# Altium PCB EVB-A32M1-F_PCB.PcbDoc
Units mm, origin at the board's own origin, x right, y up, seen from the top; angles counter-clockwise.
Board outline 51 x 21 mm, 4 copper layers (L1 (Signal), L2 (GND), L3 (PWR), L4 (Signal)), stack 1.586 mm thick; 29 components, 45 nets, 292 pads, 57 vias.
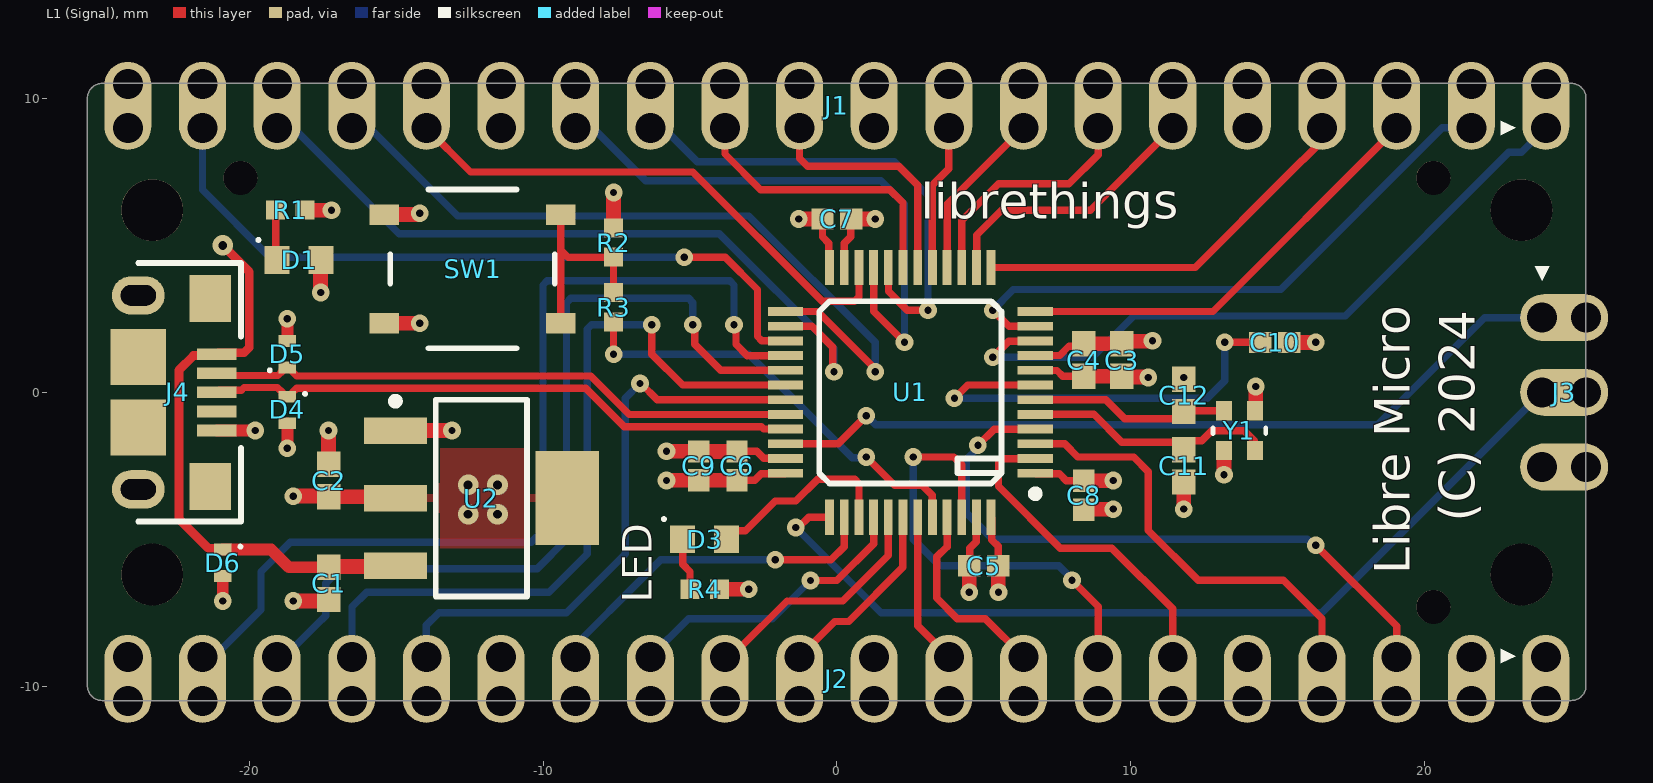
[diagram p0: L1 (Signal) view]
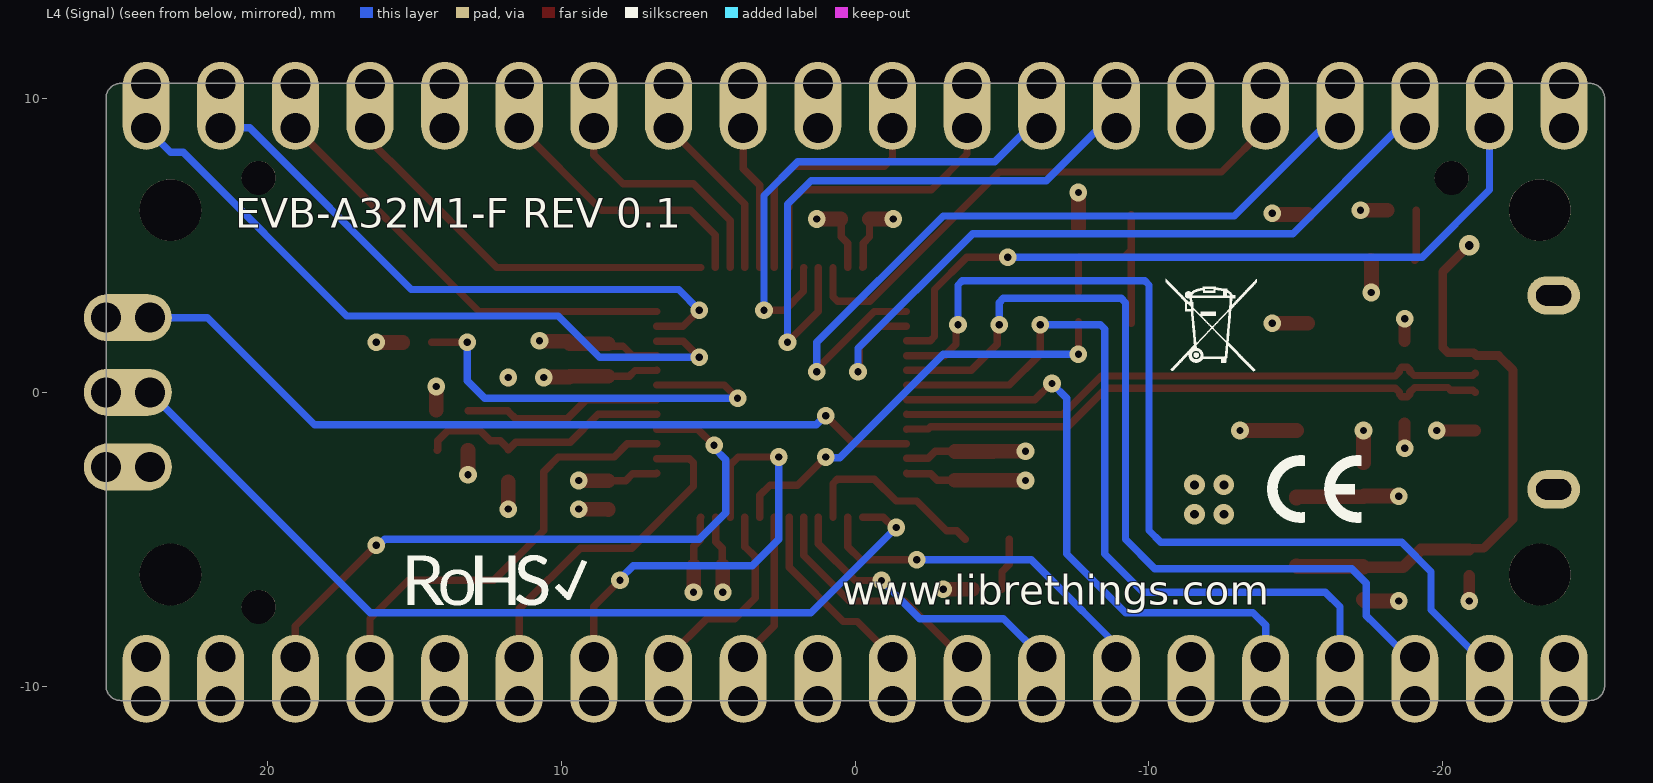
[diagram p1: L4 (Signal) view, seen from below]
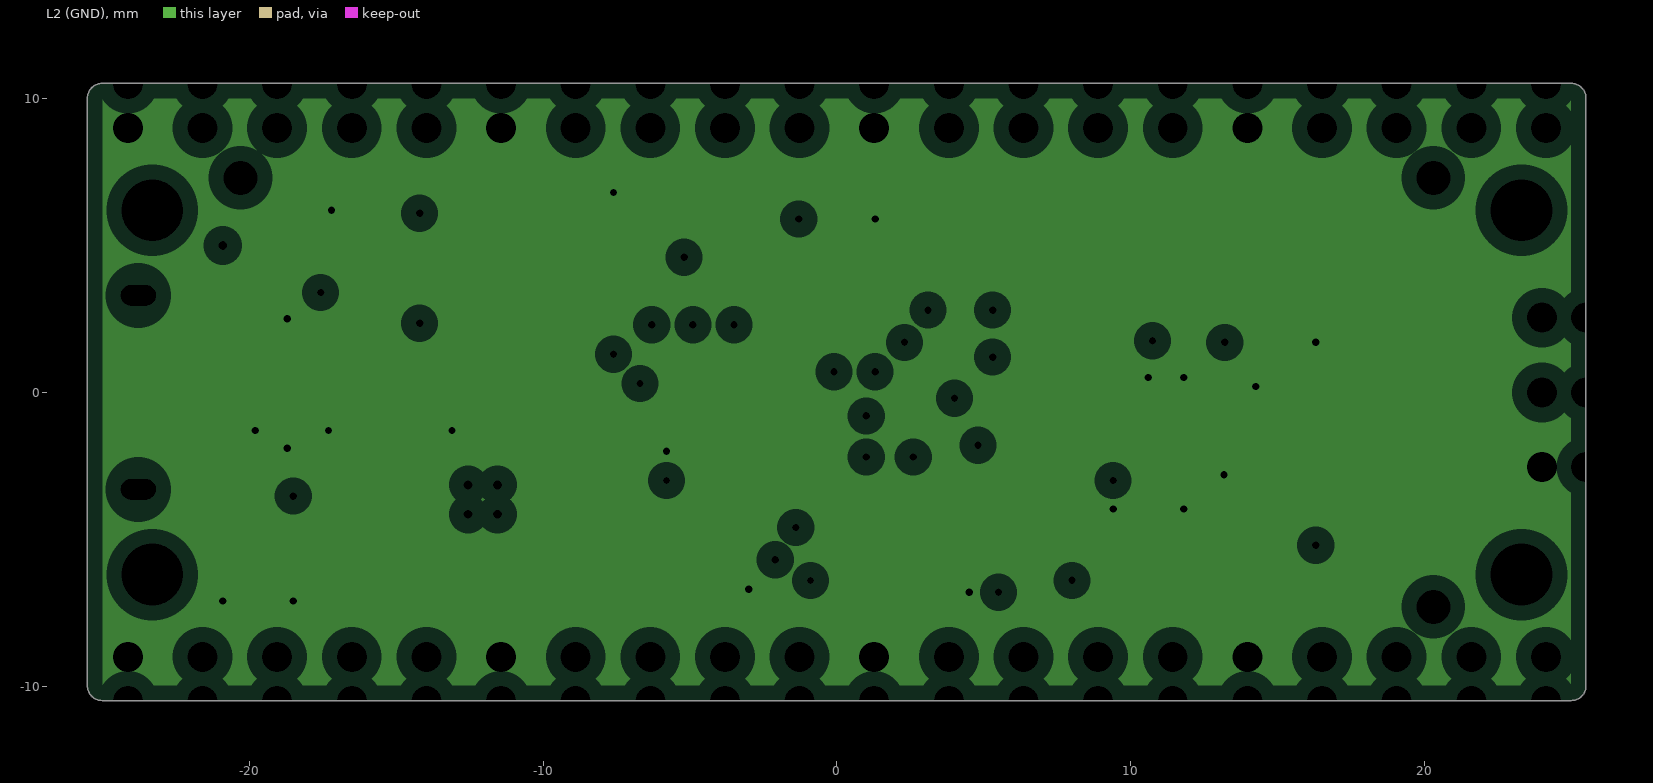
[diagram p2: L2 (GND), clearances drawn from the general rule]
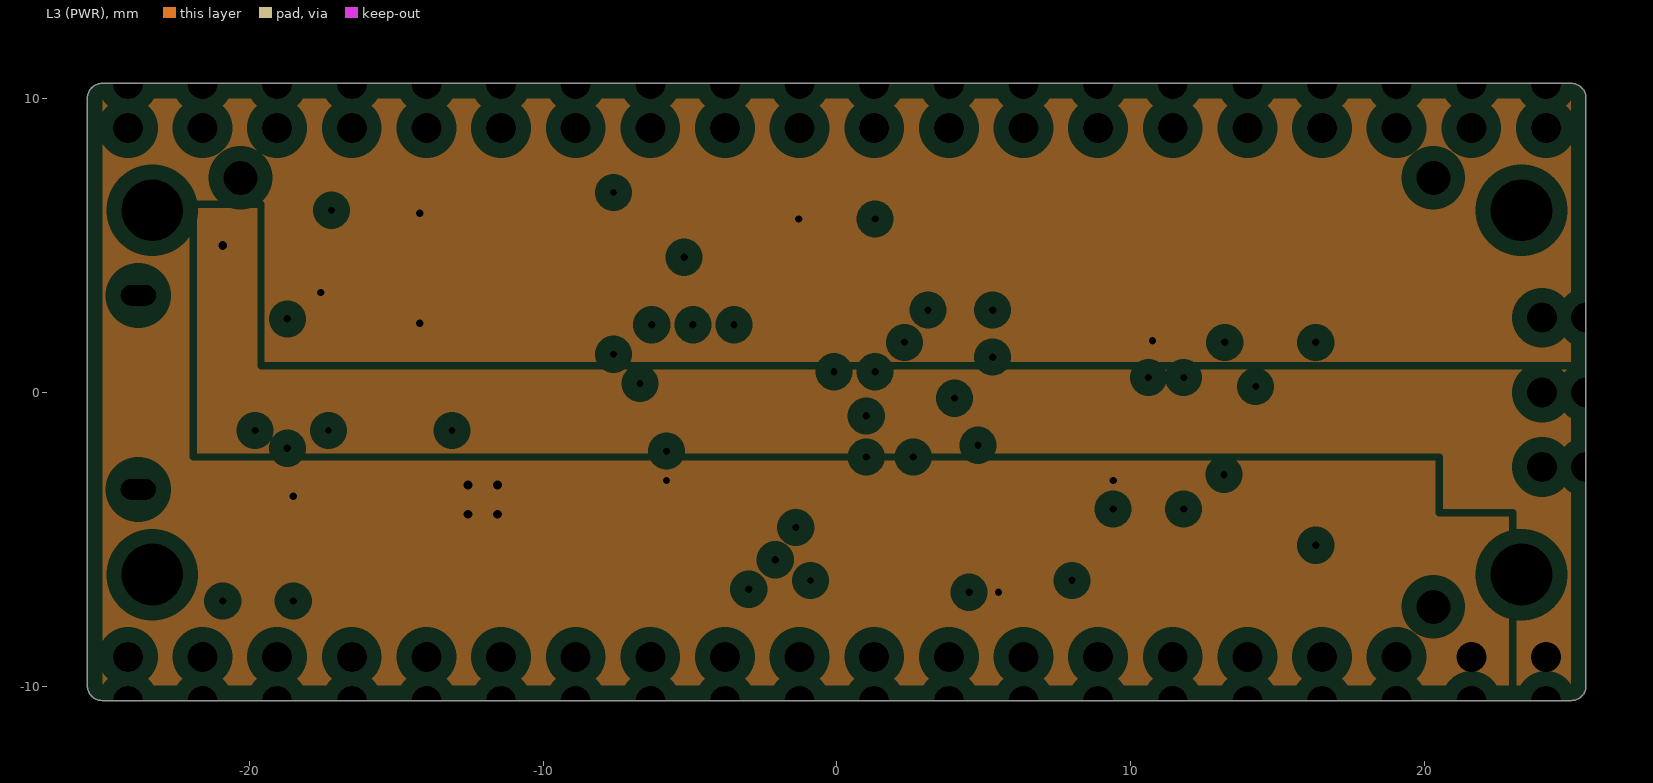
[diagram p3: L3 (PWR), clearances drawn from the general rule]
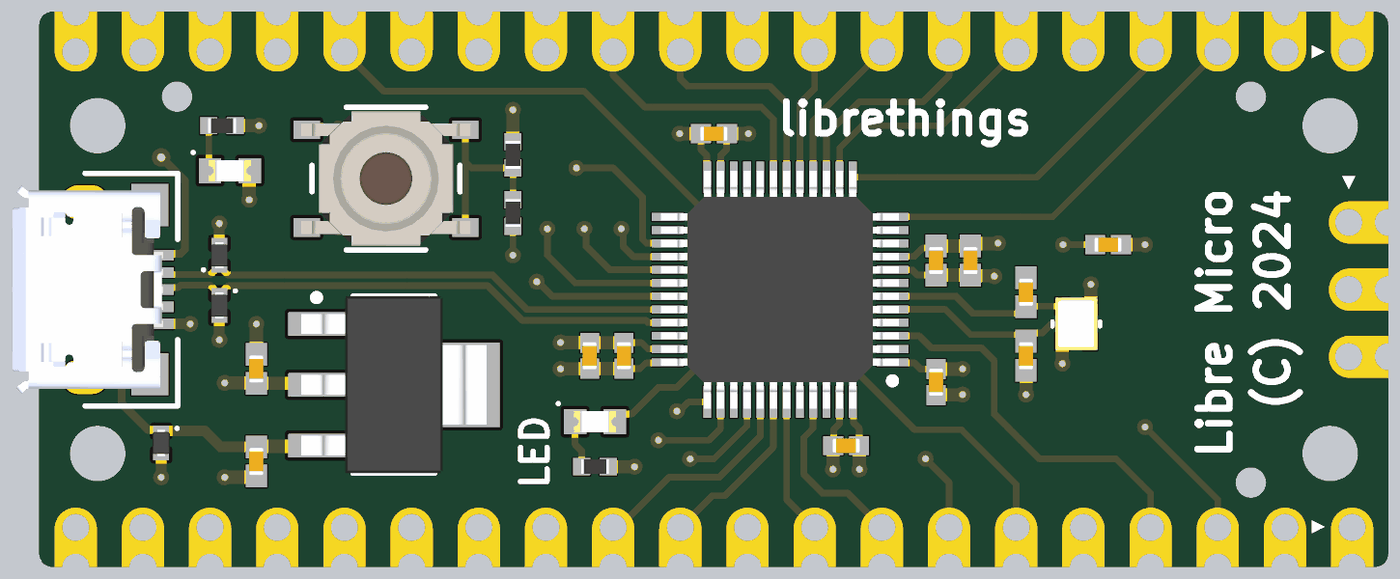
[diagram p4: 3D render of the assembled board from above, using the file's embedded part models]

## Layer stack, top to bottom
Top Solder: solder mask 0.0152, JLC-001, Dk 3.8
L1 (Signal): signal copper 0.035
PP1_7628: prepreg 0.2104, Nan Ya Plastics NP-155F 7628, Dk 4.4
L2 (GND): plane copper 0.0152, net GND
C_FR4: core 1.065, Nan Ya Plastics NP-155F FR4 / 5-7628, Dk 4.6
L3 (PWR): plane copper 0.0152, net +3V3
PP2_7628: prepreg 0.2104, Nan Ya Plastics NP-155F 7628, Dk 4.4
L4 (Signal): signal copper 0.035
Bottom Solder: solder mask 0.0152, JLC-001, Dk 3.8

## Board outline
-25.507,-9.987 -25.507,10.013 cw(c-25.007,10.013) -25.007,10.513 24.993,10.513 cw(c24.993,10.013) 25.493,10.013 25.493,-9.987 cw(c24.993,-9.987) 24.993,-10.487 -25.007,-10.487 cw(c-25.007,-9.987)

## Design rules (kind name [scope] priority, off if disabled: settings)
BoardOutlineClearance [IsText = 'True'] p1: gap=0.3 ignorepadtopadclearanceinfootprint=FALSE
Clearance ClearanceCastellated [InPadClass('Castellated')] p1: gap=0 ignorepadtopadclearanceinfootprint=FALSE
Clearance [All] p2: gap=0.25 ignorepadtopadclearanceinfootprint=FALSE except(0.1: Arc-Arc Arc-Track Track-Track; 0.15: SMDPad-SMDPad; 0.22: Arc-SMDPad Track-SMDPad; 0.27: Arc-Via Arc-Hole Track-Via Track-Hole; 0.5: THPad-THPad)
DiffPairsRouting [InDifferentialPairClass('DIFF_USB')] p1: maxlimit=0.16 minlimit=0.16 mostfreqgap=0.16 toplayer_minwidth=0.25 toplayer_maxwidth=0.25 toplayer_prefwidth=0.25 bottomlayer_minwidth=0.25 bottomlayer_maxwidth=0.25 bottomlayer_prefwidth=0.25 impedanceprofiledriven=TRUE impedanceprofileid={08012B50-AAB2-4C45-ABE7-EA8999D4259F} impedanceprofilevalue=90.000000 maxuncoupledlength=12.7
HoleSize NPTHSlotSize [HoleType = 'Slot' && PadIsPlated = 'False'] p1: absolutevalues=TRUE maxlimit=5.6 minlimit=1 maxpercent=80.000 minpercent=20.000
HoleSize PTHSlotSize [HoleType = 'Slot' && PadIsPlated = 'True'] p2: absolutevalues=TRUE maxlimit=5.6 minlimit=0.5 maxpercent=80.000 minpercent=20.000
HoleSize PTHSize [PadIsPlated = 'True'] p3: absolutevalues=TRUE maxlimit=6.35 minlimit=0.2 maxpercent=80.000 minpercent=20.000
HoleSize NPTHSize [PadIsPlated = 'False'] p4: absolutevalues=TRUE maxlimit=6.3 minlimit=0.2 maxpercent=80.000 minpercent=20.000
HoleToHoleClearance HoleToHoleClearanceCastellated [InPadClass('Castellated')] p1: gap=0.254 allowstackedmicrovias=TRUE
HoleToHoleClearance [All] p2: gap=0.5 allowstackedmicrovias=TRUE
MinimumAnnularRing MinimumAnnularRingCastellated [InPadClass('Castellated')] p1: minimumring=0
MinimumAnnularRing PTHSlotMinimumAnnularRing_1 [HoleType = 'Slot' && PadIsPlated = 'True'] p2: minimumring=0.3
MinimumAnnularRing PTHMinimumAnnularRing [PadIsPlated = 'True'] p3: minimumring=0.3
MinimumAnnularRing ViaMinimumAnnularRing [IsVia] p4: minimumring=0.15
MinimumSolderMaskSliver [All] p1: minsoldermaskwidth=0.1
PlaneClearance [All] p1: clearance=0.508
PlaneConnect [All] p1: pad.planeconnectstyle=Relief pad.reliefexpansion=0.508 pad.reliefentries=4 pad.reliefconductorwidth=0.254 pad.reliefairgap=0.254 via.planeconnectstyle=Direct via.reliefexpansion=0.508 via.reliefentries=4 via.reliefconductorwidth=0.254 via.reliefairgap=0.254
PolygonConnect [All] p1: thpad.connectstyle=Relief thpad.reliefconductorwidth=0.254 thpad.reliefentries=4 thpad.polygonreliefangle="90 Angle" thpad.airgapwidth=0.254 smdpad.connectstyle=Relief smdpad.reliefconductorwidth=0.254 smdpad.reliefentries=4 smdpad.polygonreliefangle="90 Angle" smdpad.airgapwidth=0.254 via.connectstyle=Direct via.reliefconductorwidth=0.254 via.reliefentries=4 via.polygonreliefangle="90 Angle" via.airgapwidth=0.254
RoutingVias [All] p1: holewidth=0.25 width=0.6 viastyle="Through Hole" minholewidth=0.2 minwidth=0.5 maxholewidth=0.3 maxwidth=0.7
ShortCircuit ShortCircuitCastellated [InPadClass('Castellated')] p1: allowed=TRUE
ShortCircuit [All] p2: allowed=FALSE
SilkToSilkClearance [All] p1: silktosilkclearance=0.3
SilkToSolderMaskClearance [IsPad] p1: minsilkscreentomaskgap=0.15 clearancetoexposedcopper=TRUE
SolderMaskExpansion [All] p1: expansion=0.127 istentingtop=FALSE
SupplyNets "Schematic Supply Nets_5" [InNet('VBUS')] p1: voltage=0.000
SupplyNets "Schematic Supply Nets_4" [InNet('GND')] p2: voltage=0.000
SupplyNets "Schematic Supply Nets" [InNet('+3V3')] p3: voltage=0.000
UnRoutedNet [All] p1: checkbadconnections=TRUE
Width [All] p1: maxlimit=0.5 minlimit=0.1 preferedwidth=0.25
20 further rules are at their usual default settings.

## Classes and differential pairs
pad class Castellated: J1-0 J1-1 J1-1B J1-1T J1-2 J1-2B J1-2T J1-3 J1-3B J1-3T J1-4 J1-4B J1-4T J1-5 J1-5B J1-5T J1-6 J1-6B J1-6T J1-7 J1-7B J1-7T J1-8 J1-8B J1-8T J1-9 J1-9B J1-9T J1-10 J1-10B J1-10T J1-11 J1-11B J1-11T J1-12 J1-12B J1-12T J1-13 J1-13B J1-13T J1-14 J1-14B J1-14T J1-15 J1-15B J1-15T J1-16 J1-16B J1-16T J1-17 J1-17B J1-17T J1-18 J1-18B J1-18T J1-19 J1-19B J1-19T J1-20 J1-20B J1-20T J2-0 J2-1 J2-1B J2-1T J2-2 J2-2B J2-2T J2-3 J2-3B J2-3T J2-4 J2-4B J2-4T J2-5 J2-5B J2-5T J2-6 J2-6B J2-6T J2-7 J2-7B J2-7T J2-8 J2-8B J2-8T J2-9 J2-9B J2-9T J2-10 J2-10B J2-10T J2-11 J2-11B J2-11T J2-12 J2-12B J2-12T J2-13 J2-13B J2-13T J2-14 J2-14B J2-14T J2-15 J2-15B J2-15T J2-16 J2-16B J2-16T J2-17 J2-17B J2-17T J2-18 J2-18B J2-18T J2-19 J2-19B J2-19T J2-20 J2-20B J2-20T J3-0 J3-1 J3-1B J3-1T J3-2 J3-2B J3-2T J3-3 J3-3B J3-3T
differential pair class DIFF_USB: USB_D
differential pair USB_D: +USB_D_P -USB_D_N

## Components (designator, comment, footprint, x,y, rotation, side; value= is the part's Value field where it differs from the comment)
C1 "CC0402MRX5R6BB105" C_Yageo_CC_0402_A -17.3,-6.5 r90 top value=1uF
C2 "CC0402MRX5R6BB105" C_Yageo_CC_0402_A -17.3,-3 r270 top value=1uF
C3 "CC0402MRX5R6BB105" C_Yageo_CC_0402_A 9.7,1.1 r90 top value=1uF
C4 "CC0402KRX7R7BB103" C_Yageo_CC_0402_A 8.4,1.1 r90 top value=10nF
C5 "CL05B104KP5NNNC" C_Samsung_CL_0402_A 5,-5.9 r0 top value=100nF
C6 "CL05B104KP5NNNC" C_Samsung_CL_0402_A -3.4,-2.5 r270 top value=100nF
C7 "CL05B104KP5NNNC" C_Samsung_CL_0402_A 0,5.9 r180 top value=100nF
C8 "CL05B104KP5NNNC" C_Samsung_CL_0402_A 8.4,-3.5 r90 top value=100nF
C9 "CL05A475MP5NRNC" C_Samsung_CL_0402_A -4.7,-2.5 r270 top value=4.7uF
C10 "CL05B104KP5NNNC" C_Samsung_CL_0402_A 14.9,1.7 r180 top value=100nF
C11 "CC0402JRNPO9BN150" C_Yageo_CC_0402_A 11.8,-2.5 r90 top value=15pF
C12 "CC0402JRNPO9BN150" C_Yageo_CC_0402_A 11.8,-0.1 r270 top value=15pF
D1 "LTST-C190GKT" D_LED_Lite-On_Green_0603_A -18.3,4.5 r0 top
D3 "LTST-C190GKT" D_LED_Lite-On_Green_0603_A -4.5,-5 r0 top
D4 "D5V0F1U2S9-7" D_TVS_Uni_Diodes_SOD-923_B -18.7,-0.6 r270 top value=5E-13F
D5 "D5V0F1U2S9-7" D_TVS_Uni_Diodes_SOD-923_B -18.7,1.3 r90 top value=5E-13F
D6 "D5V0F1U2S9-7" D_TVS_Uni_Diodes_SOD-923_B -20.9,-5.8 r270 top value=5E-13F
J1 "PPPC201LFBN-RC" J_Cast_TH20_Top_2.54mm 0,9.75 r180 top
J2 "PPPC201LFBN-RC" J_Cast_TH20_Bottom_2.54mm 0,-9.75 r180 top
J3 "PPPC031LFBN-RC" J_Cast_TH3_Bottom_2.54mm 24.75,0 r270 top
J4 "10118193-0001LF" J_USB_Micro-B_Amphenol_10118193-0001LF -23.775,0 r270 top
R1 "RC0402FR-071KL" R_Yageo_RCL_0402_A -18.6,6.2 r180 top value=1kR
R2 "RC0402FR-0710KL" R_Yageo_RCL_0402_A -7.6,5.1 r270 top value=10kR
R3 "RC0402FR-071KL" R_Yageo_RCL_0402_A -7.6,2.9 r90 top value=1kR
R4 "RC0402FR-071KL" R_Yageo_RCL_0402_A -4.5,-6.7 r180 top value=1kR
SW1 "PTS526SK15SMTR2LFS" "SW_Tactitle_SPST_C&K_PTS526 SK15 SMTR2 LFS" -12.4,4.2 r180 top
U1 "STM32F070CBT6" U_ST_LQFP48_B 2.5,0 r180 top
U2 "TLV1117LV33DCYR" U_TI_SOT-223_B -12.1,-3.6 r0 top
Y1 "ECS-240-12-37B-CKY-TR" Y_Crystal_GND24_ECS_240-12-37B-CKY-TR 13.7,-1.3 r90 top

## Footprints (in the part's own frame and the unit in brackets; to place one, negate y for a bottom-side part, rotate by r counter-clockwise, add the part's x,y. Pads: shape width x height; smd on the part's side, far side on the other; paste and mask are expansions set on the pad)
C_Samsung_CL_0402_A [mm] "Chip Capacitor, 2-Leads, Body 1.00x0.50mm, IPC Low Density"
  rect 0.76x0.72 smd mask+0.05: 1(-0.49,0) 2(0.49,0)
  body extent -0.53,-0.28 0.53,0.28, height 0.55
C_Yageo_CC_0402_A [mm] "Yageo series CC Chip Capacitor, 2-Leads, Body 1.00x0.50mm, IPC Low Density"
  rect 0.86x0.8 smd mask+0.05: 1(-0.55,0) 2(0.55,0)
  body extent -0.53,-0.28 0.53,0.28, height 0.7
D_LED_Lite-On_Green_0603_A [mm] "Chip Diode, 2-Leads, Body 1.60x0.70mm, IPC Low Density"
  rect 0.85x0.95 smd: 1(-0.75,0) 2(0.75,0)
  silkscreen extent -1.44,0.64 -1.34,0.74, body extent -0.8,-0.4 0.8,0.4, height 0.8
D_TVS_Uni_Diodes_SOD-923_B [mm] "SODFL, 2-Leads, Body 0.60x1.00mm, IPC Medium Density"
  rect 0.4x0.6 smd: 1(-0.45,0) 2(0.45,0)
  silkscreen extent -0.6,0.55 -0.5,0.65, body extent -0.5,-0.33 0.5,0.33, height 0.4
J_Cast_TH3_Bottom_2.54mm [mm] "20 castellated pads with 2.54mm pitch through-holes"
  round 1.02 hole 1.02 paste-2539.97 mask+0: 0(-2.54,0.75) 0(0,0.75) 0(2.54,0.75) 1(-2.54,-0.75) 2(0,-0.75) 3(2.54,-0.75)
  oval 1.6x3 smd far side paste-2539.97 mask+0: 1B(-2.54,0) 2B(0,0) 3B(2.54,0)
  oval 1.6x3 smd paste-2539.97 mask+0: 1T(-2.54,0) 2T(0,0) 3T(2.54,0)
J_Cast_TH20_Bottom_2.54mm [mm] "20 castellated pads with 2.54mm pitch through-holes"
  round 1.02 hole 1.02 paste-2539.97 mask+0: 0(-24.13,0.75) 0(-21.59,0.75) 0(-19.05,0.75) 0(-16.51,0.75) 0(-13.97,0.75) 0(-11.43,0.75) 0(-8.89,0.75) 0(-6.35,0.75) 0(-3.81,0.75) 0(-1.27,0.75) 0(1.27,0.75) 0(3.81,0.75) 0(6.35,0.75) 0(8.89,0.75) 0(11.43,0.75) 0(13.97,0.75) 0(16.51,0.75) 0(19.05,0.75) 0(21.59,0.75) 0(24.13,0.75) 1(-24.13,-0.75) 2(-21.59,-0.75) 3(-19.05,-0.75) 4(-16.51,-0.75) 5(-13.97,-0.75) 6(-11.43,-0.75) 7(-8.89,-0.75) 8(-6.35,-0.75) 9(-3.81,-0.75) 10(-1.27,-0.75) 11(1.27,-0.75) 12(3.81,-0.75) 13(6.35,-0.75) 14(8.89,-0.75) 15(11.43,-0.75) 16(13.97,-0.75) 17(16.51,-0.75) 18(19.05,-0.75) 19(21.59,-0.75) 20(24.13,-0.75)
  oval 1.6x3 smd far side paste-2539.97 mask+0: 1B(-24.13,0) 2B(-21.59,0) 3B(-19.05,0) 4B(-16.51,0) 5B(-13.97,0) 6B(-11.43,0) 7B(-8.89,0) 8B(-6.35,0) 9B(-3.81,0) 10B(-1.27,0) 11B(1.27,0) 12B(3.81,0) 13B(6.35,0) 14B(8.89,0) 15B(11.43,0) 16B(13.97,0) 17B(16.51,0) 18B(19.05,0) 19B(21.59,0) 20B(24.13,0)
  oval 1.6x3 smd paste-2539.97 mask+0: 1T(-24.13,0) 2T(-21.59,0) 3T(-19.05,0) 4T(-16.51,0) 5T(-13.97,0) 6T(-11.43,0) 7T(-8.89,0) 8T(-6.35,0) 9T(-3.81,0) 10T(-1.27,0) 11T(1.27,0) 12T(3.81,0) 13T(6.35,0) 14T(8.89,0) 15T(11.43,0) 16T(13.97,0) 17T(16.51,0) 18T(19.05,0) 19T(21.59,0) 20T(24.13,0)
J_Cast_TH20_Top_2.54mm [mm] "20 castellated pads with 2.54mm pitch through-holes"
  round 1.02 hole 1.02 paste-2539.97 mask+0: 0(-24.13,-0.75) 0(-21.59,-0.75) 0(-19.05,-0.75) 0(-16.51,-0.75) 0(-13.97,-0.75) 0(-11.43,-0.75) 0(-8.89,-0.75) 0(-6.35,-0.75) 0(-3.81,-0.75) 0(-1.27,-0.75) 0(1.27,-0.75) 0(3.81,-0.75) 0(6.35,-0.75) 0(8.89,-0.75) 0(11.43,-0.75) 0(13.97,-0.75) 0(16.51,-0.75) 0(19.05,-0.75) 0(21.59,-0.75) 0(24.13,-0.75) 1(-24.13,0.75) 2(-21.59,0.75) 3(-19.05,0.75) 4(-16.51,0.75) 5(-13.97,0.75) 6(-11.43,0.75) 7(-8.89,0.75) 8(-6.35,0.75) 9(-3.81,0.75) 10(-1.27,0.75) 11(1.27,0.75) 12(3.81,0.75) 13(6.35,0.75) 14(8.89,0.75) 15(11.43,0.75) 16(13.97,0.75) 17(16.51,0.75) 18(19.05,0.75) 19(21.59,0.75) 20(24.13,0.75)
  oval 1.6x3 smd far side paste-2539.97 mask+0: 1B(-24.13,0) 2B(-21.59,0) 3B(-19.05,0) 4B(-16.51,0) 5B(-13.97,0) 6B(-11.43,0) 7B(-8.89,0) 8B(-6.35,0) 9B(-3.81,0) 10B(-1.27,0) 11B(1.27,0) 12B(3.81,0) 13B(6.35,0) 14B(8.89,0) 15B(11.43,0) 16B(13.97,0) 17B(16.51,0) 18B(19.05,0) 19B(21.59,0) 20B(24.13,0)
  oval 1.6x3 smd paste-2539.97 mask+0: 1T(-24.13,0) 2T(-21.59,0) 3T(-19.05,0) 4T(-16.51,0) 5T(-13.97,0) 6T(-11.43,0) 7T(-8.89,0) 8T(-6.35,0) 9T(-3.81,0) 10T(-1.27,0) 11T(1.27,0) 12T(3.81,0) 13T(6.35,0) 14T(8.89,0) 15T(11.43,0) 16T(13.97,0) 17T(16.51,0) 18T(19.05,0) 19T(21.59,0) 20T(24.13,0)
J_USB_Micro-B_Amphenol_10118193-0001LF [mm] "USB - micro B USB 2.0 Receptacle Connector 5 Position Surface Mount, Right Angle; Through Hole"
  rect 0.4x1.35 smd mask+0.05: 1(-1.3,2.675) 2(-0.65,2.675) 3(0,2.675) 4(0.65,2.675) 5(1.3,2.675)
  rect 1.6x1.4 smd mask+0.05: 6(-3.2,2.45) 7(3.2,2.45)
  rect 1.9x1.9 smd mask+0.05: 8(1.2,0) 9(-1.2,0)
  oval 1.3x1.8 hole 0.7 slot 1.2 at 90 deg mask+0.05: 10(3.3,0) 11(-3.3,0)
  silkscreen extent -4.4,0 4.4,3.5, body extent -3.93,-2.76 3.93,2.95, height 2.81
R_Yageo_RCL_0402_A [mm] "Yageo series RC_L Chip Resistor, 2-Leads, Body 1.00x0.50mm, IPC Low Density"
  rect 0.65x0.65 smd mask+0.05: 1(-0.5,0) 2(0.5,0)
  body extent -0.53,-0.28 0.53,0.28, height 0.4
"SW_Tactitle_SPST_C&K_PTS526 SK15 SMTR2 LFS" [mm]
  rect 1x0.7 smd: 1(-3,1.85) 2(-3,-1.85) 3(3,1.85) 4(3,-1.85)
  silkscreen extent -2.8,-2.7 2.8,2.7, body extent -3.2,-2.55 3.2,2.55, height 1.5
U_ST_LQFP48_B [mm] "LQFP, 48-Leads, Body 9.00x9.00mm, Pitch 0.50mm, IPC Medium Density"
  rect 1.2x0.3 smd mask+0.05: 1(-4.25,2.75) 2(-4.25,2.25) 3(-4.25,1.75) 4(-4.25,1.25) 5(-4.25,0.75) 6(-4.25,0.25) 7(-4.25,-0.25) 8(-4.25,-0.75) 9(-4.25,-1.25) 10(-4.25,-1.75) 11(-4.25,-2.25) 12(-4.25,-2.75) 25(4.25,-2.75) 26(4.25,-2.25) 27(4.25,-1.75) 28(4.25,-1.25) 29(4.25,-0.75) 30(4.25,-0.25) 31(4.25,0.25) 32(4.25,0.75) 33(4.25,1.25) 34(4.25,1.75) 35(4.25,2.25) 36(4.25,2.75)
  rect 0.3x1.2 smd mask+0.05: 13(-2.75,-4.25) 14(-2.25,-4.25) 15(-1.75,-4.25) 16(-1.25,-4.25) 17(-0.75,-4.25) 18(-0.25,-4.25) 19(0.25,-4.25) 20(0.75,-4.25) 21(1.25,-4.25) 22(1.75,-4.25) 23(2.25,-4.25) 24(2.75,-4.25) 37(2.75,4.25) 38(2.25,4.25) 39(1.75,4.25) 40(1.25,4.25) 41(0.75,4.25) 42(0.25,4.25) 43(-0.25,4.25) 44(-0.75,4.25) 45(-1.25,4.25) 46(-1.75,4.25) 47(-2.25,4.25) 48(-2.75,4.25)
  silkscreen extent -4.38,-3.1 3.1,3.57, body extent -4.5,-4.5 4.5,4.5, height 1.55
U_TI_SOT-223_B [mm] "SOT223, 4-Leads, Body 6.50x7.00mm (avg), Pitch 2.30mm, IPC Medium Density"
  rect 2.15x0.9 smd: 1(-2.925,2.3) 2(-2.925,0) 3(-2.925,-2.3)
  rect 2.15x3.2 smd: 4(2.925,0)
  silkscreen extent -3.05,-3.35 1.55,3.42, body extent -3.5,-3.35 3.5,3.35, height 1.8
Y_Crystal_GND24_ECS_240-12-37B-CKY-TR [mm]
  rect 0.65x0.55 smd mask+0.05: 1(-0.675,-0.525) 2(0.675,-0.525) 3(0.675,0.525) 4(-0.675,0.525)
  silkscreen extent -0.1,-0.9 0.1,0.9, body extent -1,-0.8 1,0.8, height 0.51

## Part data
C1 C2 C3: library part CMP-001-00016-11, "Multilayer Ceramic Capacitor, 1 uF, 50 V, ± 10%, X5R, 0402 [1005 Metric]", Case Code (Imperial)=0402, Case Code (Metric)=1005, Dielectric=X5R, LCSC Part Number=C113791, Max Operating Temperature=85°C, Min Operating Temperature=-55°C, Temperature Coefficient=30ppm/°C, Tolerance=20%, Voltage Rating=10V
C4: library part CMP-001-00029-1, "Multilayer Ceramic Capacitor, 0.01 uF, 16 V, ± 10%, X7R, 0402 [1005 Metric]", Case Code (Imperial)=0402, Case Code (Metric)=1005, Dielectric=X7R, Insulation Resistance=10GR, Max Operating Temperature=125°C, Min Operating Temperature=-55°C, Package Quantity=1, Temperature Coefficient=30ppm/°C, Tolerance=10%, Voltage Rating=16V
C5 C6 C7 C8 C10: library part CMP-001-00023-3, "Multilayer Ceramic Capacitor, 0.1 uF, 10 V, ± 10%, X7R, 0402 [1005 Metric]", Case Code (Imperial)=0402, Case Code (Metric)=1005, Dielectric=X7R, Max Operating Temperature=125°C, Min Operating Temperature=-55°C, Package Quantity=1, Tolerance=10%, Voltage Rating=10V
C9: library part CMP-001-00024-3, "Multilayer Ceramic Capacitor, 4.7 uF, 10 V, ± 20%, X5R, 0402 [1005 Metric]", Case Code (Imperial)=0402, Case Code (Metric)=1005, Dielectric=X5R, Max Operating Temperature=85°C, Min Operating Temperature=-55°C, Tolerance=20%, Voltage Rating=10V
C11 C12: library part CMP-001-00017-14, "Multilayer Ceramic Capacitor, 15 pF, 10 V, ± 5%, X7R, 0402 [1005 Metric]", Case Code (Imperial)=0402, Case Code (Metric)=1005, Dielectric=C0G, Dielectric Material=Ceramic, Insulation Resistance=100GR, Max Operating Temperature=125°C, Min Operating Temperature=-55°C, Package Quantity=1, Temperature Coefficient=30ppm/°C, Tolerance=5%, Voltage=50V
D1 D3: library part CMP-007-00001-3, "LED Uni-Color Green 565nm 2-Pin Chip LED T/R", Case Code (Imperial)=0603, Case Code (Metric)=1608, Color=Green, Forward Current=30mA, Forward Voltage=2.1V, Lens Color=Colorless, Max Operating Temperature=85°C, Min Operating Temperature=-55°C, Package Quantity=1, Power Dissipation=100mW, Reverse Voltage=5V, Test Current=10mA, Voltage=2V
D4 D5 D6: library part CMP-004-00007-2, "Diode TVS Dual Uni-Dir 5.5V 250000W 2-Pin SOD-923 T/R", Breakdown Voltage=6V, Case/Package=SOD-923-2, Clamping Voltage=10V, Max Operating Temperature=150°C, Max Power Dissipation=250mW, Max Reverse Leakage Current=100nA, Max Surge Current=1.5A, Min Operating Temperature=-65°C, Package Quantity=10000, Peak Pulse Power=250kW, Power Line Protection=Yes, Reverse Standoff Voltage=5.5V
J1 J2: library part CMP-002-00009-9, "20 Position Total Single Row 2.54 mm Pitch Straight Female Header", Flammability Rating="UL94 V-0", Insulation Color=Black, Max Operating Temperature=105°C, Min Operating Temperature=-40°C, Voltage Rating=250V
J3: library part CMP-002-00004-17, "3 Position Total Single Row 2.54 mm Pitch Straight Female Header", Flammability Rating="UL94 V-0", Insulation Color=Black, Max Operating Temperature=105°C, Min Operating Temperature=-40°C, Voltage Rating=250V
J4: library part CMP-002-00002-12, "Usb Connector, 5 Contact(S), Female, Right Angle, Surface Mount Terminal, Locking, Receptacle", Color=Black, Current Rating=1.8A, Flammability Rating="UL94 V-0", Insulation Resistance=1GR, Max Operating Temperature=85°C, Max Voltage Rating (AC)=100V, Min Operating Temperature=-55°C, Package Quantity=1200
R1 R3 R4: library part CMP-009-00002-11, "SMD Chip Resistor, 1 kOhm, ± 1%, 62.5 mW, 0402 [1005 Metric], Thick Film, General Purpose", Case Code (Imperial)=0402, Case Code (Metric)=1005, Max Operating Temperature=155°C, Max Power Dissipation=63mW, Min Operating Temperature=-55°C, Power Rating=62.5mW, Resistance Tolerance=1%, Resistor Type="Thick Film", Temperature Coefficient=100ppm/°C, Voltage Rating=50V
R2: library part CMP-009-00003-11, "SMD Chip Resistor, 10 kOhm, ± 1%, 62.5 mW, 0402 [1005 Metric], Thick Film, General Purpose", Case Code (Imperial)=0402, Case Code (Metric)=1005, Max Operating Temperature=155°C, Max Power Dissipation=63mW, Min Operating Temperature=-55°C, Power Rating=62.5mW, Resistance Tolerance=1%, Resistor Type="Thick Film", Temperature Coefficient=100ppm/°C, Voltage Rating=50V
SW1: library part CMP-011-00002-2, "Switch Tactile N.O. SPST Round Button Gull Wing 0.05A 12VDC 200000Cycles 2.45N SMD T/R", Contact Current Rating=50mA, Contact Resistance=100mR, Max Operating Temperature=70°C, Min Operating Temperature=-20°C, Operating Force=260gf, Ratings=IP40, Voltage Rating (DC)=12V
U1: library part CMP-020-00002-1, "IC MCU 32BIT 128KB FLASH 48LQFP", Case/Package=LQFP, Clock Frequency=48MHz, Max Operating Temperature=85°C, Max Power Dissipation=364mW, Max Supply Voltage=3.6V, Min Operating Temperature=-40°C, Min Supply Voltage=2.4V, Operating Supply Voltage=3.3V, Package Quantity=250
U2: library part CMP-019-00002-2, "LDO Regulator Pos 3.3V 1A 4-Pin(3+Tab) SOT-223 T/R", Case/Package=SOT-223-4, Dropout Voltage=570mV, Max Operating Temperature=125°C, Max Output current=1A, Max Output Voltage=3.3V, Max Supply Voltage=5.5V, Min Input Voltage=2V, Min Operating Temperature=-40°C, Operating Supply Current=50uA, Package Quantity=2500, Power Supply Rejection Ratio (PSRR)=75dB
Y1: library part CMP-003-00000-11, "Crystal 24MHz ±10ppm (Tol) ±10ppm (Stability) 12pF FUND 50Ohm 4-Pin Mini-CSMD T/R", Case/Package="4-SMD, No Lead", Frequency=24MHz, Load Capacitance=12pF

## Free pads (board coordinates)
  round 2.1 hole 2.1 unplated mask+0: MH1(-23.3,6.2) MH2(-23.3,-6.2) MH3(23.3,-6.2) MH4(23.3,6.2)
  round 1.152 hole 1.152 unplated mask+0: TH1(-20.3,7.3) TH2(20.3,7.3) TH3(20.3,-7.3)

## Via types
v1: diameter 0.6, hole 0.25, L1 (Signal) to L4 (Signal), tented both sides, 52 vias
v2: diameter 0.7, hole 0.3, L1 (Signal) to L4 (Signal), tented both sides, 5 vias

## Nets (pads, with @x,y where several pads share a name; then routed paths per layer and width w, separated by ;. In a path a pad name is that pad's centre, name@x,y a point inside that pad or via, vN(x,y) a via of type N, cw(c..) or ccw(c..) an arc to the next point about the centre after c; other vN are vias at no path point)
3V3_LED_K: D1.1 R1.2 | length 1.7
  L1 (Signal) w0.25: R1.2 -19.1,4.55 D1.1
+3V3: C2.2 C3.2 C4.2 C5.2 C6.2 C7.2 C8.2 C9.2 D1.2 J2.2 J2.2B J2.2T SW1.3 SW1.4 U1.1 U1.9 U1.24 U1.36 U1.48 U2.2 U2.4 | length 23.4
  L1 (Signal) w0.25: C6.2 -2.79,-2.99 -2.575,-2.775 -1.775,-2.775 U1.36 ; C7.2 -0.49,5.29 -0.275,5.075 -0.275,4.275 U1.24 ; U1.48 5.275,-4.275 5.275,-5.025 5.49,-5.24 C5.2 ; U1.1 6.775,-2.775 7.575,-2.775 7.81,-3.01 C8.2 ; U1.9 6.755,1.255 7.58,1.255 7.9,1.575 8.325,1.575 C4.2
  L1 (Signal) w0.5: v1@-18.5,-3.5 -18.475,-3.525 -17.325,-3.525 C2.2 -15.025,-3.55 U2.2 ; v1@-17.6,3.4 -17.575,3.425 -17.575,4.475 D1.2 ; SW1.3 v1(-14.2,2.35) ; SW1.4 -14.272,6.05 -14.227,6.095 v1(-14.2,6.095) ; v1(-5.8,-3) -5.795,-2.995 -4.705,-2.995 C9.2 C6.2 ; v1(-1.3,5.9) C7.2 ; C5.2 5.495,-5.905 5.495,-6.795 v1(5.5,-6.8) ; C8.2 8.405,-3.005 9.395,-3.005 v1(9.4,-3) ; C4.2 C3.2 9.787,1.737 10.72,1.737 v1(10.739,1.756)
  other v1: -18.5,-3.53 -17.57,3.4
  other v2: -12.55,-4.15 -11.55,-4.15 -12.55,-3.15 -11.55,-3.15
BOOT0: R3.1 U1.44 | length 14.7
  L1 (Signal) w0.25: v1(-7.6,1.3) R3.1 ; v1(1,-2.2) 1.958,-3.158 2.896,-3.158 3.245,-3.507 3.245,-3.775 U1.44@3.245,-4.245
  L4 (Signal) w0.25: v1(-7.6,1.3) -3,1.3 0.523,-2.223 0.977,-2.223 v1(1,-2.2)
GND: C1.1 C2.1 C3.1 C4.1 C5.1 C6.1 C7.1 C8.1 C9.1 C10.1 C11.1 C12.1 D4.2 D5.2 D6.2 J1.5 J1.5B J1.5T J1.10 J1.10B J1.10T J1.15 J1.15B J1.15T J1.20 J1.20B J1.20T J2.5 J2.5B J2.5T J2.10 J2.10B J2.10T J2.15 J2.15B J2.15T J2.20 J2.20B J2.20T J3.3 J3.3B J3.3T J4.5 R1.1 R2.1 R4.1 U1.8 U1.23 U1.35 U1.47 U2.1 Y1.2 Y1.4 | length 29
  L1 (Signal) w0.25: C6.1 -2.728,-2.01 -2.493,-2.245 -1.755,-2.245 U1.35 ; U1.23 0.255,4.255 0.255,5.08 0.475,5.3 0.475,5.885 C7.1 ; C5.1 4.525,-5.885 4.525,-5.3 4.745,-5.08 4.745,-4.255 U1.47 ; U1.8 6.755,0.745 7.493,0.745 7.688,0.55 C4.1
  L1 (Signal) w0.4: J4.5 v1(-19.8,-1.3) ; v1(-20.9,-7.1) D6.2 ; v1(-18.7,-1.9) D4.2 ; D5.2 v1(-18.7,2.5)
  L1 (Signal) w0.5: v1(-18.5,-7.1) -17.35,-7.1 C1.1 ; R1.1 v1(-17.2,6.2) ; C2.1@-17.3,-2.4 v1(-17.3,-1.3) ; U2.1 v1(-13.1,-1.3) ; R2.1 v1(-7.6,6.8) ; v1(-5.8,-2) -5.795,-2.005 -4.705,-2.005 C9.1 C6.1 ; R4.1 v1(-3,-6.7) ; C7.1 v1(1.3,5.9) ; v1(4.5,-6.8) 4.505,-6.795 4.505,-5.905 C5.1 ; C8.1 8.409,-3.981 9.391,-3.981 v1(9.4,-3.972) ; C4.1 C3.1 9.726,0.524 10.581,0.524 v1(10.6,0.505) ; v1(11.8,-3.972) C11.1 ; C12.1 v1(11.8,0.505) ; Y1.4 v1(13.175,-2.8) v1@13.2,-2.8 ; Y1.2@14.25,-0.6 v1(14.25,0.2) ; C10.1 v1(16.3,1.7)
NRST: C10.2 U1.7 | length 14.9
  L1 (Signal) w0.25: v1(4,-0.2) 4.45,0.25 U1.7 ; v1(13.2,1.7) C10.2
  L4 (Signal) w0.25: v1(4,-0.2) 12.6,-0.2 13.2,0.4 v1(13.2,1.7)
OSC_IN: C11.2 U1.5 Y1.1 | length 8.7
  L1 (Signal) w0.25: U1.5 8.75,-0.75 9.7,-1.7 11.55,-1.7 C11.2 11.8,-1.92 12.075,-1.645 12.417,-1.645 12.757,-1.305 13.859,-1.305 14.2,-1.646 14.2,-1.95 Y1.1
OSC_OUT: C12.2 U1.6 Y1.3 | length 6.8
  L1 (Signal) w0.25: U1.6 9.15,-0.25 9.8,-0.9 11.55,-0.9 C12.2 11.825,-0.625 Y1.3
PA0: J1.1 J1.1B J1.1T U1.10 | length 23.7
  L1 (Signal) w0.25: v1(5.3,1.2) 5.845,1.745 6.745,1.745 U1.10
  L4 (Signal) w0.25: v1(5.3,1.2) 8.7,1.2 10.1,2.6 17.3,2.6 22.87,8.17 23.3,8.17 J1.1
PA1: J1.2 J1.2B J1.2T U1.11 | length 20.5
  L1 (Signal) w0.25: v1(5.3,2.8) 5.855,2.245 6.745,2.245 U1.11
  L4 (Signal) w0.25: v1(5.3,2.8) 6,3.5 15.1,3.5 20.6,9 J1.2
PA2: J1.3 J1.3B J1.3T U1.12 | length 14.9
  L1 (Signal) w0.25: U1.12 12.8,2.75 J1.3
PA3: J1.4 J1.4B J1.4T U1.13 | length 13.5
  L1 (Signal) w0.25: U1.13 12.199,4.25 15.349,7.4 16.363,8.414 16.363,8.853 J1.4
PA4: J1.6 J1.6B J1.6T U1.14 | length 9.3
  L1 (Signal) w0.25: U1.14 4.755,4.255 4.755,5.355 5.6,6.2 8.63,6.2 J1.6
PA5: J1.7 J1.7B J1.7T U1.15 | length 8.1
  L1 (Signal) w0.25: U1.15 4.25,5.85 5.5,7.1 7.9,7.1 8.89,8.09 J1.7
PA6: J1.8 J1.8B J1.8T U1.16 | length 5.8
  L1 (Signal) w0.25: U1.16 3.75,6.4 J1.8
PA7: J1.9 J1.9B J1.9T U1.17 | length 5
  L1 (Signal) w0.25: U1.17 3.25,7.05 3.81,7.61 J1.9
PA8: J2.18 J2.18B J2.18T U1.29 | length 29.5
  L1 (Signal) w0.25: v1(-4.9,2.3) -4.833,2.233 -4.833,1.633 -3.95,0.75 U1.29
  L4 (Signal) w0.25: J2.18 -18.842,-9 -18.591,-8.749 -18.549,-8.749 -17.7,-7.9 -17.4,-7.6 -17.4,-6.5 -16.9,-6 -10.2,-6 -9.2,-5 -9.2,3.054 -9.054,3.2 -5.046,3.2 -4.9,3.054 v1(-4.9,2.3)
PA9: J2.17 J2.17B J2.17T U1.30 | length 26.3
  L1 (Signal) w0.25: v1(-6.3,2.3) -6.3,1.3 -5.25,0.25 U1.30
  L4 (Signal) w0.25: J2.17 -16.5,-8.99 -16.5,-7.3 -16,-6.8 -9.8,-6.8 -8.5,-5.5 -8.5,2.154 -8.354,2.3 v1(-6.3,2.3)
PA10: J2.16 J2.16B J2.16T U1.31 | length 20
  L1 (Signal) w0.25: v1(-6.7,0.3) -6.669,0.3 -6.119,-0.25 U1.31
  L4 (Signal) w0.25: J2.16 -13.97,-7.93 -13.54,-7.5 -9.2,-7.5 -7.2,-5.5 -7.2,-0.2 v1(-6.7,0.3)
PA15: J2.14 J2.14B J2.14T U1.38 | length 11.9
  L1 (Signal) w0.25: v1(-2.1,-5.7) -0.2,-5.7 0.25,-5.25 U1.38
  L4 (Signal) w0.25: J2.14 -8.743,-8.853 -8.743,-8.443 -6.8,-6.5 -6,-5.7 v1(-2.1,-5.7)
PB0: J1.11 J1.11B J1.11T U1.18 | length 8.2
  L1 (Signal) w0.25: J1.11 -1.27,7.97 -1,7.7 2.1,7.7 2.75,7.05 U1.18
PB1: J1.12 J1.12B J1.12T U1.19 | length 9.8
  L1 (Signal) w0.25: J1.12 -3.81,8.11 -2.6,6.9 1.8,6.9 2.25,6.45 U1.19
PB2: J1.13 J1.13B J1.13T U1.20 | length 16.7
  L1 (Signal) w0.25: U1.20 1.755,4.245 1.755,3.445 2.4,2.8 v1(3.1,2.8)
  L4 (Signal) w0.25: J1.13 -6.203,8.853 -5.753,8.853 -4.75,7.85 1.95,7.85 3.1,6.7 v1(3.1,2.8)
PB4: J2.13 J2.13B J2.13T U1.40 | length 10.1
  L1 (Signal) w0.25: v1(-0.9,-6.405) -0.005,-6.405 1.25,-5.15 U1.40
  L4 (Signal) w0.25: J2.13 -5.05,-7.7 -2.195,-7.7 v1(-0.9,-6.405)
PB5: J2.12 J2.12B J2.12T U1.41 | length 8.3
  L1 (Signal) w0.25: J2.12 -3.602,-9 -3.331,-8.729 -3.329,-8.729 -1.7,-7.1 0.2,-7.1 1.75,-5.55 U1.41
PB6: J2.11 J2.11B J2.11T U1.42 | length 6.5
  L1 (Signal) w0.25: J2.11 -0.07,-7.8 0.4,-7.8 2.245,-5.955 2.245,-4.255 U1.42
PB7: J2.9 J2.9B J2.9T U1.43 | length 5.2
  L1 (Signal) w0.25: U1.43 2.75,-7.94 J2.9
PB8: J2.8 J2.8B J2.8T U1.45 | length 6.7
  L1 (Signal) w0.25: U1.45 3.75,-5.25 3.4,-5.6 3.4,-7 4.1,-7.7 5.05,-7.7 J2.8
PB9: J2.7 J2.7B J2.7T U1.46 | length 15.3
  L1 (Signal) w0.25: v1(2.6,-2.2) 3.982,-2.2 4.25,-2.468 U1.46 ; v1(8,-6.4) 8.89,-7.29 J2.7
  L4 (Signal) w0.25: v1(2.6,-2.2) 2.6,-5 3.5,-5.9 7.554,-5.9 8,-6.346 v1(8,-6.4)
PB10: J1.14 J1.14B J1.14T U1.21 | length 20
  L1 (Signal) w0.25: U1.21 1.25,2.75 v1(2.3,1.7)
  L4 (Signal) w0.25: J1.14 -8.809,8.919 -8.219,8.919 -6.5,7.2 1.5,7.2 2.3,6.4 v1(2.3,1.7)
PB11: J1.16 J1.16B J1.16T U1.22 | length 18.2
  L1 (Signal) w0.25: J1.16 -12.47,7.5 -4.9,7.5 -0.5,3.1 0.6,3.1 0.75,3.25 U1.22
PB12: J1.17 J1.17B J1.17T U1.25 | length 25.8
  L1 (Signal) w0.25: U1.25 -0.65,2.75 1.125,0.975 1.125,0.97 1.3,0.795 v1(1.3,0.7)
  L4 (Signal) w0.25: J1.17 -16.439,8.929 -15.829,8.929 -12.9,6 -3,6 1.3,1.7 v1(1.3,0.7)
PB13: J1.18 J1.18B J1.18T U1.26 | length 25.6
  L1 (Signal) w0.25: U1.26 -1.745,2.245 -0.845,2.245 -0.137,1.537 -0.137,0.737 v1(-0.1,0.7)
  L4 (Signal) w0.25: J1.18 -18.949,8.899 -18.399,8.899 -14.9,5.4 -4,5.4 -0.1,1.5 v1(-0.1,0.7)
PB14: J1.19 J1.19B J1.19T U1.27 | length 25
  L1 (Signal) w0.25: v1(-5.2,4.6) -3.8,4.6 -2.7,3.5 -2.7,1.9 -2.555,1.755 -1.755,1.755 U1.27
  L4 (Signal) w0.25: J1.19 -21.59,6.89 -19.3,4.6 v1(-5.2,4.6)
PB15: J2.19 J2.19B J2.19T U1.28 | length 33
  L1 (Signal) w0.25: v1(-3.5,2.3) -3.433,2.233 -3.433,1.633 -3.05,1.25 U1.28
  L4 (Signal) w0.25: J2.19 -21.443,-8.853 -21.053,-8.853 -19.6,-7.4 -19.6,-6.1 -18.6,-5.1 -10.4,-5.1 -10,-4.7 -10,3.654 -9.854,3.8 -3.646,3.8 -3.5,3.654 v1(-3.5,2.3)
PC13: J2.6 J2.6B J2.6T U1.2 | length 11.4
  L1 (Signal) w0.25: U1.2 6.745,-2.255 5.646,-2.255 5.5,-2.401 5.5,-3.2 7.6,-5.3 9.36,-5.3 11.43,-7.37 J2.6
PC14: J2.4 J2.4B J2.4T U1.3 | length 14.7
  L1 (Signal) w0.25: U1.3 7.75,-1.75 8.2,-2.2 10.1,-2.2 10.6,-2.7 10.6,-4.7 12.3,-6.4 15.2,-6.4 16.51,-7.71 J2.4
PC15: J2.3 J2.3B J2.3T U1.4 | length 21.9
  L1 (Signal) w0.25: v1(4.8,-1.8) 5.35,-1.25 U1.4 ; v1(16.3,-5.2) 19.05,-7.95 J2.3
  L4 (Signal) w0.25: v1(4.8,-1.8) 4.8,-1.895 4.4,-2.295 4.4,-4.1 5.3,-5 16.005,-5 16.205,-5.2 v1(16.3,-5.2)
PROG_LED: D3.2 U1.39 | length 6.6
  L1 (Signal) w0.25: D3.2 -3.46,-4.71 -3.11,-4.71 -2.1,-3.7 -1.4,-3.7 -0.655,-2.955 0.604,-2.955 0.75,-3.101 U1.39
PROG_LED_K: D3.1 R4.2 | length 1.8
  L1 (Signal) w0.25: D3.1 -5.25,-5.85 -5,-6.1 R4.2
SW_BOOT0: R2.2 R3.2 SW1.1 SW1.2 | length 6.8
  L1 (Signal) w0.25: SW1.1 -9.4,4.846 ; SW1.2 -9.4,4.846 ; R3.2 R2.2 -9.154,4.6 -9.4,4.846
SWCLK: J3.2 J3.2B J3.2T U1.37 | length 31
  L1 (Signal) w0.25: v1(-1.4,-4.6) -1.305,-4.6 -0.955,-4.25 U1.37
  L4 (Signal) w0.25: v1(-1.4,-4.6) 1.5,-7.5 16.5,-7.5 J3.2
SWDIO: J3.1 J3.1B J3.1T U1.34 | length 27.8
  L1 (Signal) w0.25: U1.34 0.05,-1.75 v1(1,-0.8)
  L4 (Signal) w0.25: v1(1,-0.8) 1.021,-0.8 1.321,-1.1 18.4,-1.1 22.04,2.54 J3.1
USB_D_N: D5.1 J4.2 U1.32 | length 20.2
  L1 (Signal) w0.25: J4.2 -21.025,0.575 -20.27,0.575 -19.021,0.575 -18.875,0.721 -18.875,0.775 -18.8,0.85 -18.6,0.85 -18.525,0.775 -18.525,0.701 -18.379,0.555 -8.375,0.555 -7.065,-0.755 -1.755,-0.755 U1.32
USB_D_P: D4.1 J4.3 U1.33 | length 20.3
  L1 (Signal) w0.25: J4.3 -21.025,0.075 -20.27,0.075 -20.18,0.165 -19.041,0.165 -18.875,-0.001 -18.875,-0.075 -18.8,-0.15 -18.6,-0.15 -18.525,-0.075 -18.525,-0.001 -18.379,0.145 -8.545,0.145 -7.235,-1.165 -2.573,-1.165 -2.493,-1.245 -1.755,-1.245 U1.33
VBUS: C1.2 D6.1 J2.1 J2.1B J2.1T J4.1 U2.3 | length 19.8
  L1 (Signal) w0.3: J4.1 J4.1@-21.05,1.35 ; D6.1 -20.943,-5.307 -21.393,-5.307 -22.395,-4.305 -22.395,0.753 -21.898,1.25 -21.15,1.25 J4.1@-21.05,1.35 ; v2(-20.9,5) -20,4.1 -20,1.526 -20.176,1.35 J4.1@-21.05,1.35
  L1 (Signal) w0.4: D6.1 -19.25,-5.35 -18.65,-5.95 C1.2
  L1 (Signal) w0.5: C1.2 -17.275,-5.925 -15.05,-5.925 U2.3
pads on no net: J1.0 J2.0 J3.0 J4.4 J4.6 J4.7 J4.8 J4.9 J4.10 J4.11

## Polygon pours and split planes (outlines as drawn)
+3V3 on L1 (Signal) "+3V3_L01_P000" (solid, pour order 0): -16.2,-3.1 -13.5,-3.1 -13.5,-1.9 -8,-1.9 -8,-5.3 -13.5,-5.3 -13.5,-4.1 -16.2,-4.1
GND on L2 (GND) (split plane): 24.983,-9.977 -24.997,-9.977 -24.997,10.003 24.983,10.003
+3V3 on L3 (PWR) (split plane): 24.983,1.027 -19.473,1.027 -19.473,6.4 -19.482,6.449 -19.51,6.49 -19.551,6.518 -19.6,6.527 -21.9,6.527 -21.949,6.518 -21.99,6.49 -22.018,6.449 -22.027,6.4 -22.027,2.9 -22.027,-2.2 -22.018,-2.249 -21.99,-2.29 -21.949,-2.318 -21.9,-2.327 20.373,-2.327 20.373,-4.1 20.382,-4.149 20.41,-4.19 20.451,-4.218 20.5,-4.227 22.873,-4.227 22.873,-9.977 -24.997,-9.977 -24.997,10.003 24.983,10.003
VBUS on L3 (PWR) (split plane): -19.727,0.9 -19.718,0.851 -19.69,0.81 -19.649,0.782 -19.6,0.773 24.983,0.773 24.983,-9.977 23.127,-9.977 23.127,-4.1 23.118,-4.051 23.09,-4.01 23.049,-3.982 23,-3.973 20.627,-3.973 20.627,-2.2 20.618,-2.151 20.59,-2.11 20.549,-2.082 20.5,-2.073 -21.773,-2.073 -21.773,2.9 -21.773,6.273 -19.727,6.273

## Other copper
L3 (PWR) (plane layer: these items are gaps in the copper):
  lines w0.1: 22.9,-10.6 25.6,-10.6 25.6,0.9
  lines w0.25: 22.9,-10.6 23,-10.6 23,-4.1 20.5,-4.1 20.5,-2.2 -21.9,-2.2 -21.9,2.9 -21.9,6.4 -19.6,6.4 -19.6,0.9 25.6,0.9

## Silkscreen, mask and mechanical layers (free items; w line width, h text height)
Top Overlay:
  region: 22.6,-8.725 22.6,-9.225 23.1,-8.975
  region: 22.6,9.25 22.6,8.75 23.1,9
  region: 24.25,4.3 23.75,4.3 24,3.8
  text "librethings" at 2.854,5.9 h1.2
  text "(C) 2024" at 21.7,-4.399 h1.2 r90
  text "Libre Micro" at 19.5,-6.198 h1.2 r90
  text "LED" at -6.3,-7.166 h1 r90
Bottom Overlay:
  drawing of 9 lines, arcs and shapes, not listed
  text "EVB-A32M1-F REV 0.1" at 21.094,5.6 h1
  text "www.librethings.com" at 0.43,-7.233 h1
Mechanical 1:
  the board outline again, w0.1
